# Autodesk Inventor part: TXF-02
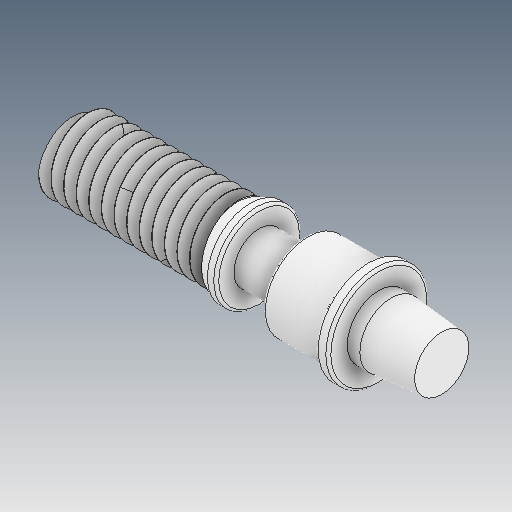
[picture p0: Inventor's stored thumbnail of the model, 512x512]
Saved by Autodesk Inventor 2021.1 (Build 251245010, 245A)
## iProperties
Created: 2021-05
Part Number: TXF-02
Material: Ogólny
Document SubType Name: Modeling
Designer: user
Density: 1 g/cm^3
Appearance: Domyślna
Author: user
Revision Number: ÈÎºÎ
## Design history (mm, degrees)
feature "ÊäÈë1"
node "Bryła1"
